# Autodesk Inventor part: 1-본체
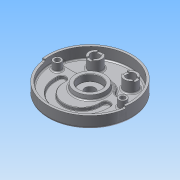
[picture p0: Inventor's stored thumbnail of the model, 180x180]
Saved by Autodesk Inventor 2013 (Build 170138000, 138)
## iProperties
Created: 2015-06
Part Number: 1-본체
Material: 알루미늄 6061
Document SubType Name: Modeling
Designer: Administrator
Density: 2.71 g/cm^3
Mass: 1070.99 g
Surface Area: 1034.49 cm^2
Volume: 395.201 cm^3
Author: Administrator
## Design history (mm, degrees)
sketch "스케치1"
  geometry: C1 r 95 at (0, 0); 1 further point
  constraints: 1 centre point, 1 coincident
  dimensions: "d0" = 190 diameter of C1
extrude "돌출1" new body sketch "스케치1" distance "d2" = 32; taper "d3" = 0 deg
sketch "스케치2"
  geometry: C1 r 95 at (0, 0) reference; C2 r 90 at (0, 0)
  constraints: 1 centre point, 1 coincident
  dimensions: "d4" = 180 diameter of C2
extrude "돌출2" cut sketch "스케치2" distance "d6" = 18; taper "d7" = 0 deg
sketch "스케치3"
  geometry: L1 (-95, 0)-(95, 0); L2 (0, 0)-(-94.075, -13.221); L3 (0, 0)-(94.075, -13.221); C1 r 90 at (0, 0) reference; A1 r 95 centre (0, 0) between (-95, 0) and (95, 0) reference; A2 r 90 centre (0, 0) between (-89.124, -12.526) and (89.124, -12.526); A3 r 95 centre (0, 0) between (-94.075, -13.221) and (94.075, -13.221)
  constraints: 8 point on circle, 6 end point, 3 coincident, 2 centre point, 2 concentric, 2 point on line, 1 horizontal, 1 midpoint
  dimensions: "d8" = 8 deg angle of L2 L1; "d10" = 8 deg angle of L3 L1
extrude "돌출3" cut sketch "스케치3" distance "d11" = 5; taper "d12" = 0 deg
sketch "스케치4"
  geometry: C1 r 95 at (0, 0) reference; C2 r 26 at (0, 0)
  constraints: 1 centre point, 1 coincident
  dimensions: "d13" = 52 diameter of C2
extrude "돌출4" join sketch "스케치4" distance "d15" = 12; taper "d16" = -15 deg
sketch "스케치5"
  geometry: L1 (90, 0)-(-90, 0); L2 (75.657, 16)-(45.033, 16); L3 (-45.033, 16)-(-75.657, 16); A1 r 90 centre (0, 0) between (-90, 0) and (90, 0) reference; A2 r 42 centre (0, 0) between (36.373, 21) and (-36.373, 21); A3 r 10 centre (-75.657, 26) between (-75.657, 16) and (-85.114, 29.25); A4 r 10 centre (-45.033, 26) between (-45.033, 16) and (-36.373, 21); A5 r 10 centre (45.033, 26) between (45.033, 16) and (36.373, 21); A6 r 10 centre (75.657, 26) between (75.657, 16) and (85.114, 29.25); A7 r 90 centre (0, 0) between (89.124, -12.526) and (-89.124, -12.526) reference; A8 r 90 centre (0, 0) between (85.114, 29.25) and (-85.114, 29.25)
  constraints: 14 point on circle, 12 tangent, 6 centre point, 6 end point, 3 equal radius, 2 coincident, 2 parallel, 1 horizontal, 1 midpoint
  dimensions: "d17" = 84 diameter of A2; "d19" = 10 radius of A3; "d21" = 16 distance between parallel lines of L1 L3; "d22" = 90 radius of A8
extrude "돌출5" cut sketch "스케치5" distance "d23" = 7; taper "d24" = 0 deg
sketch "스케치6"
  geometry: C1 r 35 at (0, 0); A1 r 42 centre (0, 0) between (36.373, 21) and (-36.373, 21) reference
  constraints: 1 centre point, 1 coincident
  dimensions: "d25" = 70 diameter of C1
extrude "돌출6" join sketch "스케치6" distance "d27" = 10; taper "d28" = -10 deg
hole "구멍1" diameter "d31" = 23; stored, may be unused: countersink angle "d35" = 90 deg, drill point angle "d37" = 118 deg; dims "d29" = 10, "d30" = 10, "d32" = 6, "d33" = 50, "d34" = 15, "d36" = 8
sketch "스케치7"
  geometry: C1 r 35 at (0, 0) reference; C2 r 9 at (-74, 0); C3 r 9 at (74, 0); A1 r 42 centre (0, 0) between (36.373, 21) and (-36.373, 21) reference; A2 r 74 centre (0, 0) between (-74, 0) and (74, 0)
  constraints: 3 centre point, 2 horizontal alignment, 2 point on circle, 1 coincident, 1 equal radius
  dimensions: "d38" = 148 diameter of A2; "d40" = 18 diameter of C3
extrude "돌출7" join sketch "스케치7" stored distance "d41" = 10; taper "d42" = 0 deg
sketch "스케치8"
  geometry: L1 (-45.033, 16)-(-75.657, 16) reference; L2 (-59, -19)-(59, -19); L3 (-59, -14)-(59, -14); L4 (-59, -19)-(-59, -14); L5 (-41, -19)-(-41, -14); L6 (41, -19)-(41, -14); L7 (59, -19)-(59, -14); L8 (-50, -19)-(-50, -14); L9 (50, -19)-(50, -14); C1 r 35 at (0, 0) reference; A1 r 59 centre (0, -19) between (-59, -19) and (59, -19); A2 r 41 centre (0, -19) between (-41, -19) and (41, -19); A3 r 50 centre (0, -19) between (-50, -19) and (50, -19); 3 further points
  constraints: 16 end point, 8 point on line, 6 point on circle, 6 tangent, 5 coincident, 4 parallel, 4 perpendicular, 3 centre point, 2 horizontal alignment, 1 midpoint, 1 vertical alignment, 4 other
  dimensions: "d43" = 59 radius of A1; "d45" = 41 radius of A2; "d46" = 19 distance of A1.centre C1.centre; "d47" = 5 distance between parallel lines of L2 L3; "d48" = 50 radius of A3
extrude "돌출8" cut sketch "스케치8" distance "d49" = 7; taper "d50" = 0 deg
sketch "스케치9"
  geometry: C1 r 15 at (-40, 52); C2 r 15 at (40, 52); C3 r 9 at (74, 0) reference; A1 r 90 centre (0, 0) between (85.114, 29.25) and (-85.114, 29.25) reference
  constraints: 2 centre point, 1 equal radius, 1 horizontal alignment
  dimensions: "d51" = 52 vertical distance of C3.centre C2.centre; "d52" = 30 diameter of C1; "d53" = 80 distance of C2.centre C1.centre; "d54" = 40 horizontal distance of A1.centre C1.centre
extrude "돌출9" join sketch "스케치9" stored distance "d55" = 7; taper "d56" = 0 deg
hole "구멍2" diameter "d68" = 20; stored, may be unused: countersink angle "d72" = 90 deg, drill point angle "d74" = 118 deg; dims "d66" = 10, "d67" = 10, "d69" = 6, "d70" = 50, "d71" = 15, "d73" = 8
hole "구멍3" diameter "d77" = 20; stored, may be unused: countersink angle "d81" = 90 deg, drill point angle "d83" = 118 deg; dims "d75" = 10, "d76" = 10, "d78" = 6, "d79" = 50, "d80" = 15, "d82" = 8
sketch "스케치10"
  geometry: L1 (6, -16)-(-6, -16); L2 (-6, -16)-(-6, 16); L3 (-6, 16)-(6, 16); L4 (6, 16)-(6, -16); L5 (6, -16)-(-6, 16); L6 (-6, -16)-(6, 16); L7 (64, 6)-(96, 6); L8 (96, 6)-(96, -6); L9 (96, -6)-(64, -6); L10 (64, -6)-(64, 6); L11 (64, 6)-(96, -6); L12 (96, 6)-(64, -6); C1 r 15 at (0, 0) reference; C2 r 15 at (80, 0) reference; 1 further point
  constraints: 24 end point, 4 midpoint, 4 parallel, 2 horizontal, 2 perpendicular
  dimensions: "d57" = 12 distance of L2.end L3.end; "d61" = 32 distance of L3.end L1.start; "d62" = 32 distance of L7.start L7.end; "d63" = 12 distance of L7.end L8.end
extrude "돌출10" cut sketch "스케치10" distance "d64" = 3; taper "d65" = 0 deg
sketch "스케치11"
  geometry: C1 r 26 at (0, 0) reference; C2 r 95 at (0, 0) reference; A1 r 74 centre (0, 0) between (-74, 0) and (74, 0)
  constraints: 2 horizontal alignment, 2 point on circle, 1 centre point, 1 coincident
  dimensions: "d84" = 148 diameter of A1
hole "구멍4" sketch "스케치11" at (-74, 0), (74, 0) diameter "d86" = 11; stored, may be unused: countersink angle "d90" = 90 deg, drill point angle "d92" = 118 deg; dims "d87" = 6, "d88" = 18, "d89" = 11, "d91" = 8
sketch "스케치12"
  geometry: C1 r 95 at (0, 0) reference; C2 r 68 at (0, 0)
  constraints: 1 centre point, 1 coincident, 1 other
  dimensions: "d93" = 136 diameter of C2
feature "엠보싱1" sketch "스케치12" dims "d95" = 0.5, "d96" = 0
chamfer "모따기1" distance "d97" = 1; stored, may be unused: second distance "d98" = 2, angle "d99" = 45 deg
fillet "모깎기1" dims "d100" = 0.3, "d101" = 1, "d102" = 3, "d103" = 5
node "솔리드1"
node "투영된 루프1"
other parameters: "d20" = 16
